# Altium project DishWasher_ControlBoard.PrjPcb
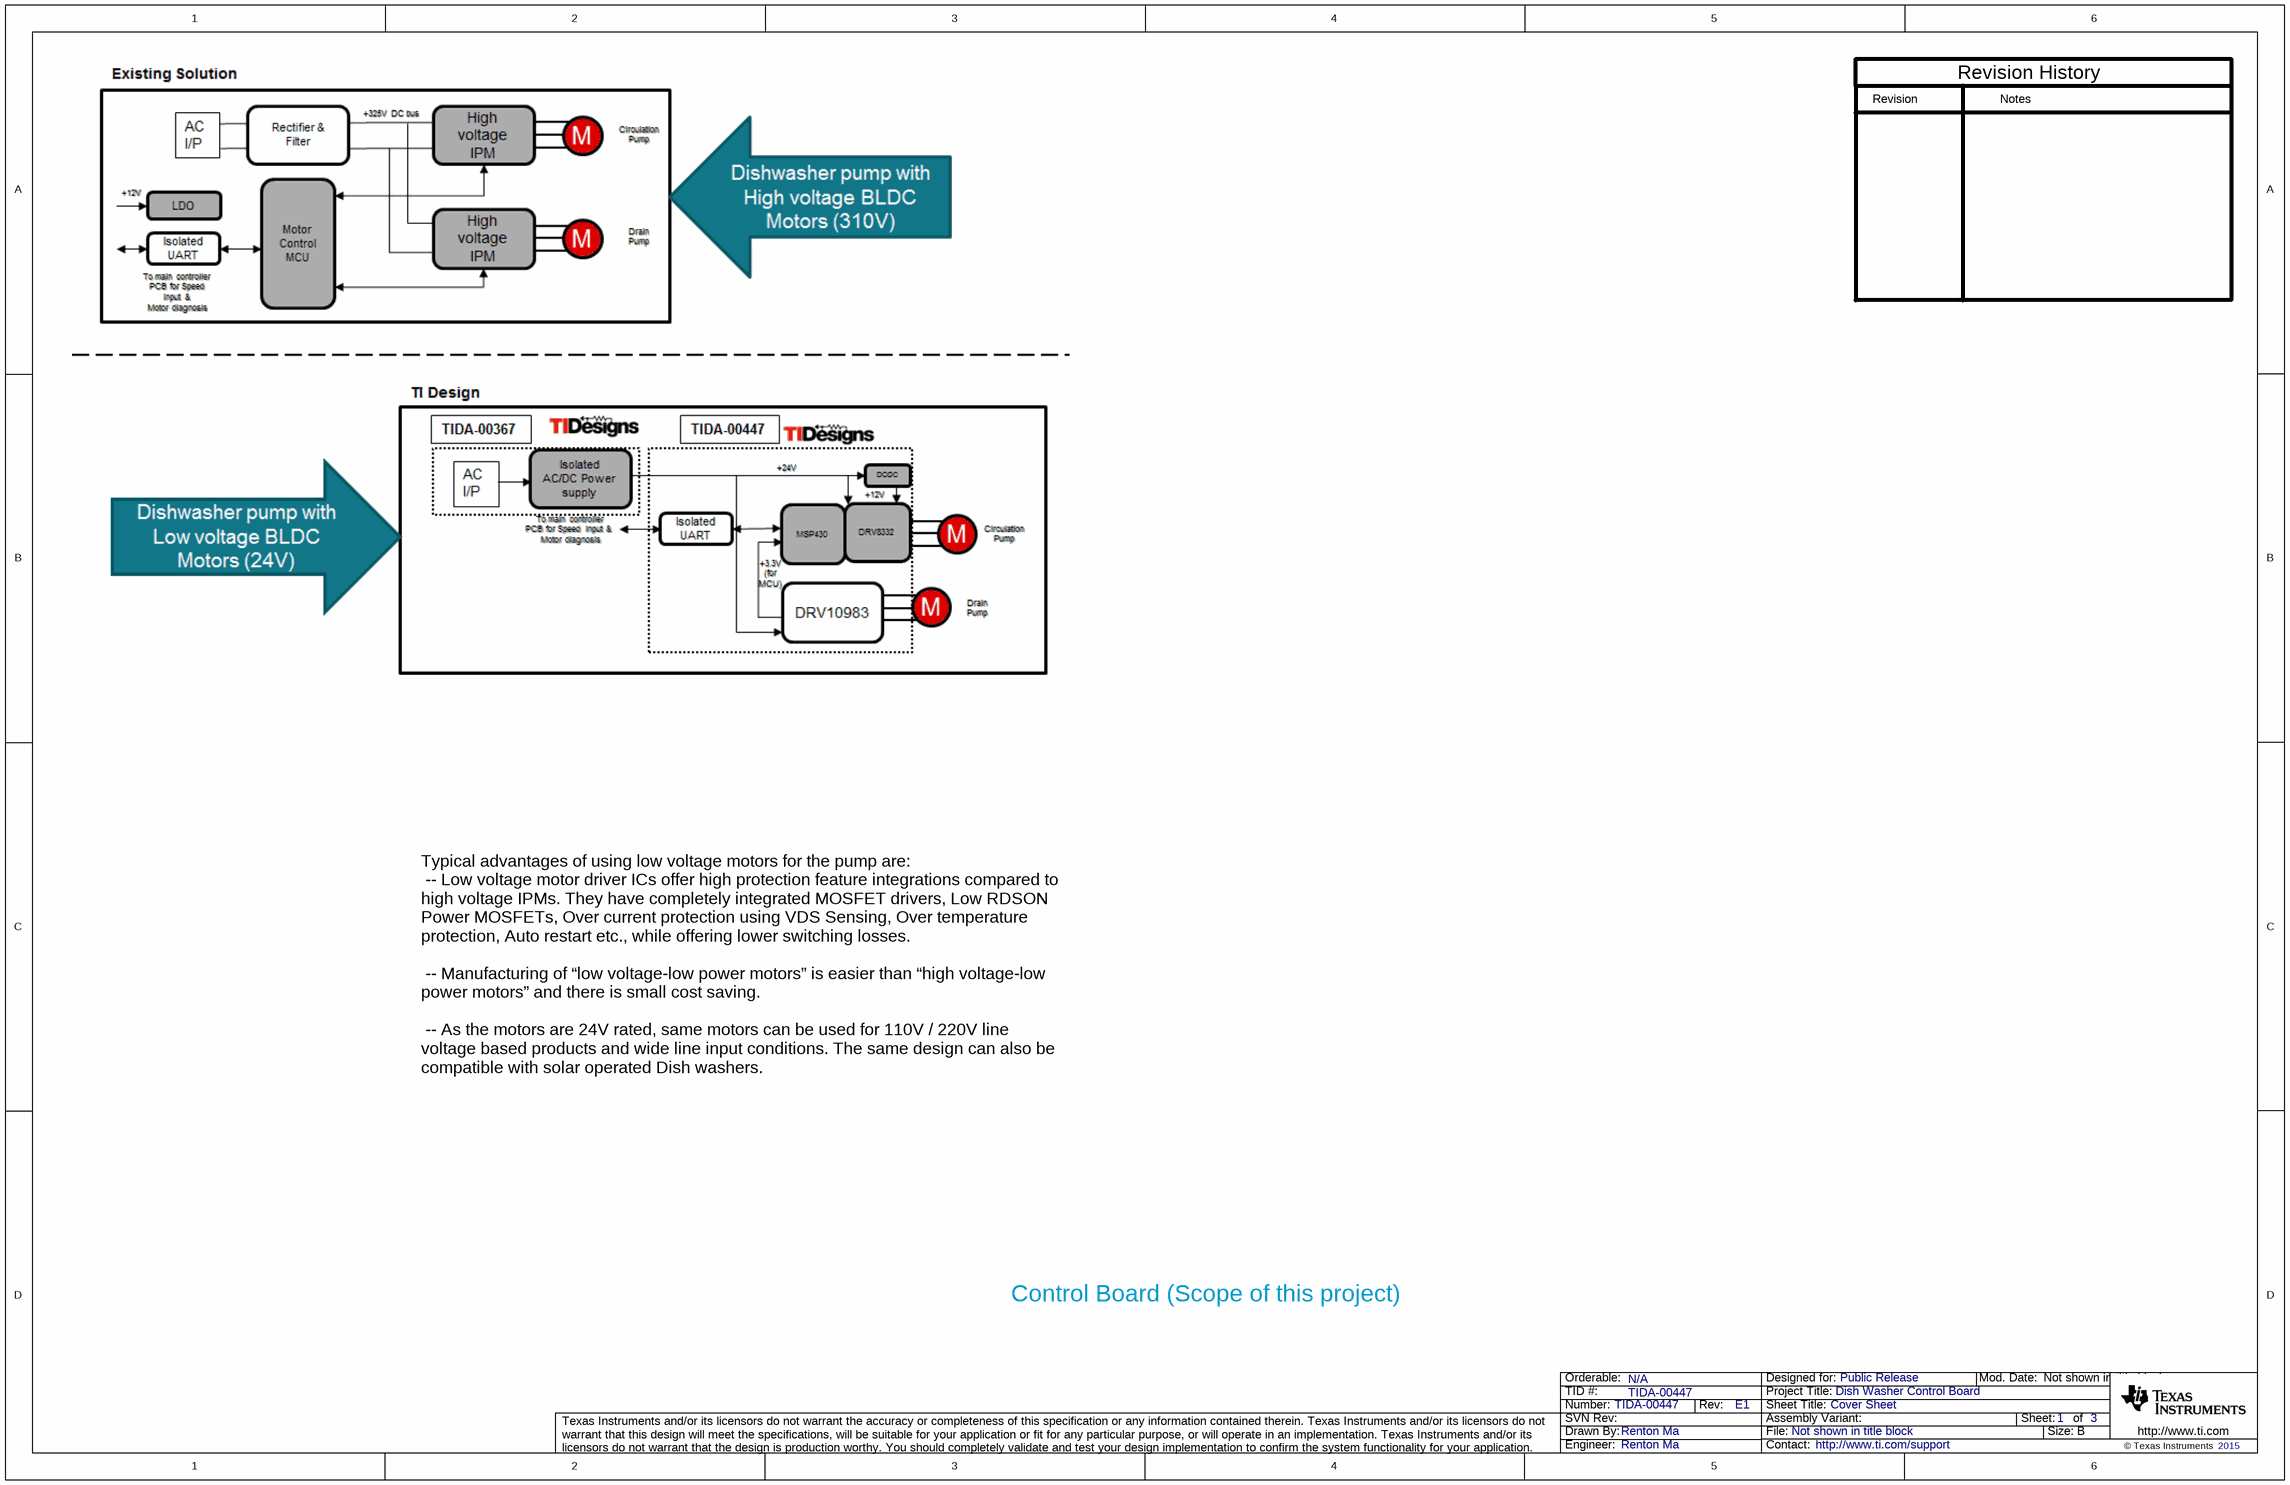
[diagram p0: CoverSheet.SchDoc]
CopyrightYear: 2015; EVM_Orderable: N/A; PCB_Layout: Who did the Layout?; PCB_Rev: E1; PRJ_Customer: Public Release; PRJ_Engineer: Renton Ma; PRJ_Number: TIDA-00447; PRJ_Title: Dish Washer Control Board; SCH_Rev: E1; TechSupport: http://www.ti.com/support; TID: TIDA-00447
4 sheets, 147 parts. Net scope: global (net labels, ports and power ports of the same name join across sheets).
Board file: TIDA00447.PcbDoc
Sheets:
  CoverSheet.SchDoc
  TID_Hardware.SchDoc
  TIDA00447_MCU+DRV10983.SchDoc
  TIDA00447_DRV8303.SchDoc

## Sheet CoverSheet.SchDoc: Cover Sheet
size 431 x 279 mm; IsUserConfigurable: Yes; Date: Not shown in title block; ApprovedBy: Not shown in title block; CheckedBy: Not shown in title block; Author: Not shown in title block; CompanyName: Not shown in title block; DrawnBy: Renton Ma; Engineer: Renton Ma; Organization: Not shown in title block; Address1: Not shown in title block; Address2: Not shown in title block; Address3: Not shown in title block; Address4: Not shown in title block; DocumentNumber: 1; Revision: Use project parameter SCH_Rev; SheetNumber: 1; SheetTotal: 3; PageSetup: Record=PageOptions¦CenterHorizontal=True¦CenterVertical=True¦PrintScale=1.00¦XCorrection=1.00¦YCorrection=1.00¦PrintKind=0¦BorderSize=5000000¦LeftOffset=0¦BottomOffset=0¦Orientation=2¦PaperLength=1000¦PaperWidth=1000¦Scale=100¦PaperSource=15¦PrintQuality=600¦MediaType=1¦DitherType=10¦PaperKind=Letter¦PrintScaleMode=1

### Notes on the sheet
- Revision
- Notes
- Revision History
- Typical advantages of using low voltage motors for the pump are:
  -- Low voltage motor driver ICs offer high protection feature integrations compared to high voltage IPMs. They have completely integrated MOSFET drivers, Low RDSON Power MOSFETs, Over current protection using VDS Sensing, Over temperature protection, Auto restart etc., while offering lower switching losses.
  -- Manufacturing of “low voltage-low power motors” is easier than “high voltage-low power motors” and there is small cost saving.
  -- As the motors are 24V rated, same motors can be used for 110V / 220V line voltage based products and wide line input conditions. The same design can also be compatible with solar operated Dish washers.
- Control Board (Scope of this project)

## Sheet TID_Hardware.SchDoc
size 431 x 279 mm; Date: Not shown in title block; ApprovedBy: Not shown in title block; CheckedBy: Not shown in title block; Author: Not shown in title block; CompanyName: Not shown in title block; Engineer: Not shown in title block; Organization: Not shown in title block; Address1: Not shown in title block; Address2: Not shown in title block; Address3: Not shown in title block; Address4: Not shown in title block; DocumentNumber: 1; Revision: Use project parameter SCH_Rev; SheetNumber: 3; SheetTotal: 3; PageSetup: Record=PageOptions¦CenterHorizontal=True¦CenterVertical=True¦PrintScale=1.00¦XCorrection=1.00¦YCorrection=1.00¦PrintKind=0¦BorderSize=5000000¦LeftOffset=0¦BottomOffset=0¦Orientation=2¦PaperLength=1000¦PaperWidth=1000¦Scale=100¦PaperSource=15¦PrintQuality=600¦MediaType=1¦DitherType=10¦PaperKind=Letter¦PrintScaleMode=1
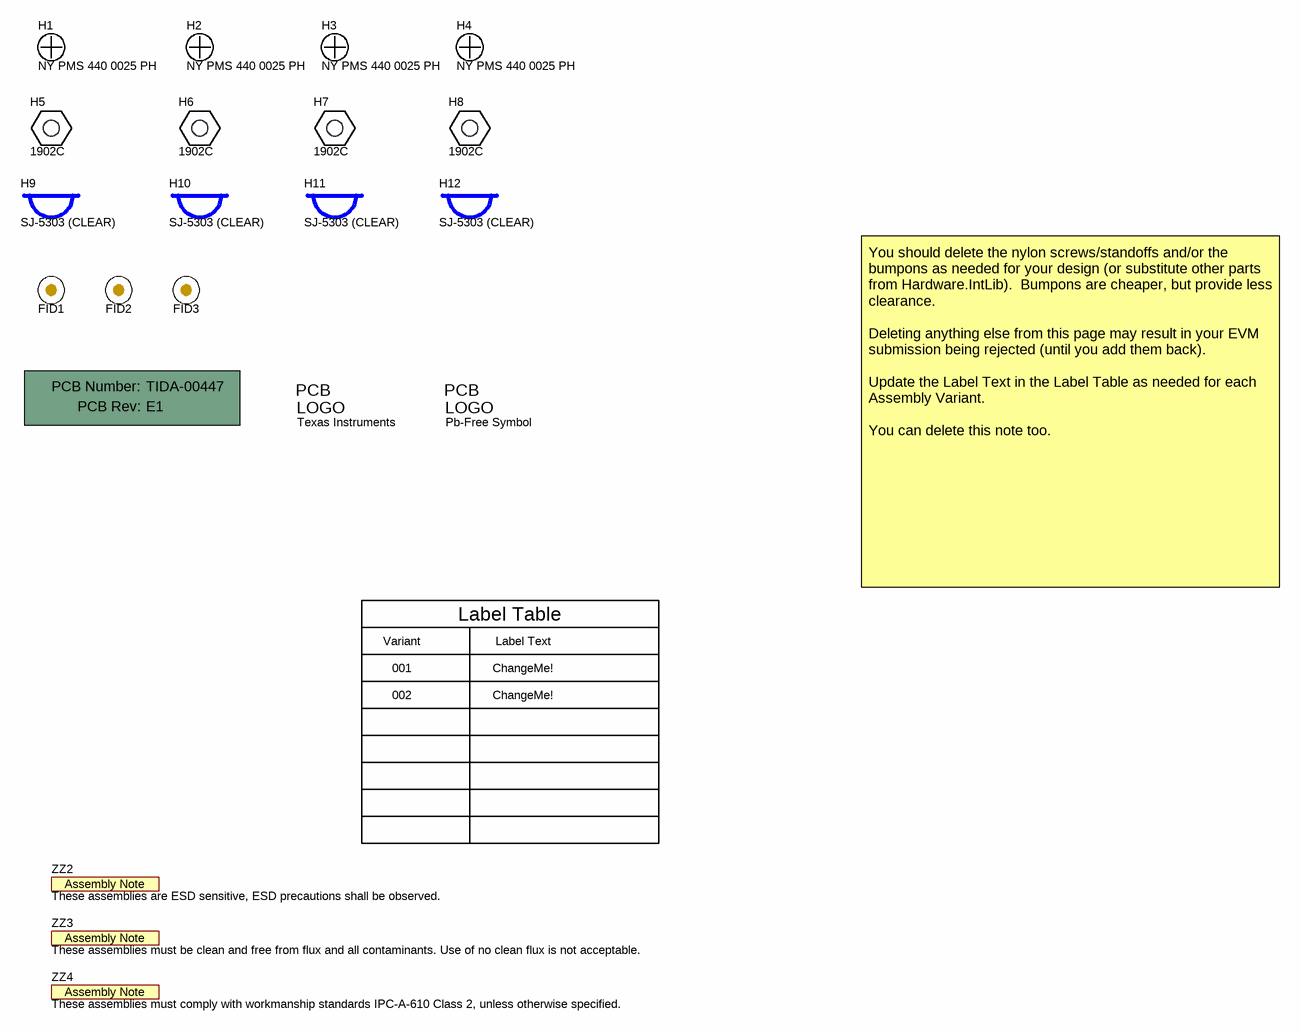
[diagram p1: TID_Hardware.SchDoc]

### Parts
!PCB  Printed Circuit Board  (value not drawn)  (mechanical)
FID1  Fiducial  [Fiducial10-20]  (value not drawn)
FID2  Fiducial  [Fiducial10-20]  (value not drawn)
FID3  Fiducial  [Fiducial10-20]  (value not drawn)
H1  NY PMS 440 0025 PH  [NY PMS 440 0025 PH]
H2  NY PMS 440 0025 PH  [NY PMS 440 0025 PH]
H3  NY PMS 440 0025 PH  [NY PMS 440 0025 PH]
H4  NY PMS 440 0025 PH  [NY PMS 440 0025 PH]
H5  1902C  [Keystone_1902C]
H6  1902C  [Keystone_1902C]
H7  1902C  [Keystone_1902C]
H8  1902C  [Keystone_1902C]
H9  SJ-5303 (CLEAR)  [Bumpon_SJ5003Transparent]
H10  SJ-5303 (CLEAR)  [Bumpon_SJ5003Transparent]
H11  SJ-5303 (CLEAR)  [Bumpon_SJ5003Transparent]
H12  SJ-5303 (CLEAR)  [Bumpon_SJ5003Transparent]
Logo1  Texas Instruments  [TI_Stacked_SolderMask_Small]  (no BOM)
Logo2  Pb-Free Symbol  [Pb-Free_Overlay_Small]  (no BOM)
ZZ2  These assemblies are ESD sensitive, ESD precautions shall be observed.  [AssemblyNote]  (no BOM)
ZZ3  These assemblies must be clean and free from flux and all contaminants. Use of no clean flux is not acceptable.  [AssemblyNote]  (no BOM)
ZZ4  These assemblies must comply with workmanship standards IPC-A-610 Class 2, unless otherwise specified.  [AssemblyNote]  (no BOM)

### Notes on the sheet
- Variant
- Label Table
- Label Text
- You should delete the nylon screws/standoffs and/or the bumpons as needed for your design (or substitute other parts from Hardware.IntLib).  Bumpons are cheaper, but provide less clearance.
  Deleting anything else from this page may result in your EVM submission being rejected (until you add them back).
  Update the Label Text in the Label Table as needed for each Assembly Variant.
  You can delete this note too.
- 001
- 002
- ChangeMe!

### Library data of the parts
!PCB = PCB: Manufacturer: Any; PartNumber: TIDA-00447; SymbolCreator: a0412235
FID1-FID3 = Fiducial: Fiducial mark.  There is nothing to buy or mount.; SymbolCreator: codlsc
H1-H4 = NY PMS 440 0025 PH: Machine Screw, Round, #4-40 x 1/4, Nylon, Philips panhead; Manufacturer: B&F Fastener Supply; CompType: Hardware; SymbolCreator: codlsc; U/M: EA
H5-H8 = 1902C: Standoff, Hex, 0.5"L #4-40 Nylon; Manufacturer: Keystone; CompType: Hardware
H9-H12 = SJ-5303 (CLEAR): Bumpon, Hemisphere, 0.44 X 0.20, Clear; Manufacturer: 3M; SymbolCreator: a0412235
Logo1 = TI_Logo: Texas Instrument Corporate Signature; SymbolCreator: codlsc
Logo2 = Pb-Free: SymbolCreator: a0412235
ZZ2-ZZ4 = AssemblyNote: SymbolCreator: codlsc

## Sheet TIDA00447_MCU+DRV10983.SchDoc: Pump Drivers
size 431 x 279 mm; Date: Not shown in title block; ApprovedBy: Not shown in title block; CheckedBy: Not shown in title block; Author: Not shown in title block; CompanyName: Not shown in title block; Engineer: Not shown in title block; Organization: Not shown in title block; Address1: Not shown in title block; Address2: Not shown in title block; Address3: Not shown in title block; Address4: Not shown in title block; DocumentNumber: 1; Revision: Use project parameter SCH_Rev; SheetNumber: 2; SheetTotal: 3; PageSetup: Record=PageOptions¦CenterHorizontal=True¦CenterVertical=True¦PrintScale=0.62¦XCorrection=1.00¦YCorrection=1.00¦PrintKind=0¦BorderSize=5000000¦LeftOffset=0¦BottomOffset=0¦Orientation=2¦PaperLength=1000¦PaperWidth=1000¦Scale=100¦PaperSource=15¦PrintQuality=600¦MediaType=1¦DitherType=10¦PaperKind=Letter¦PrintScaleMode=1
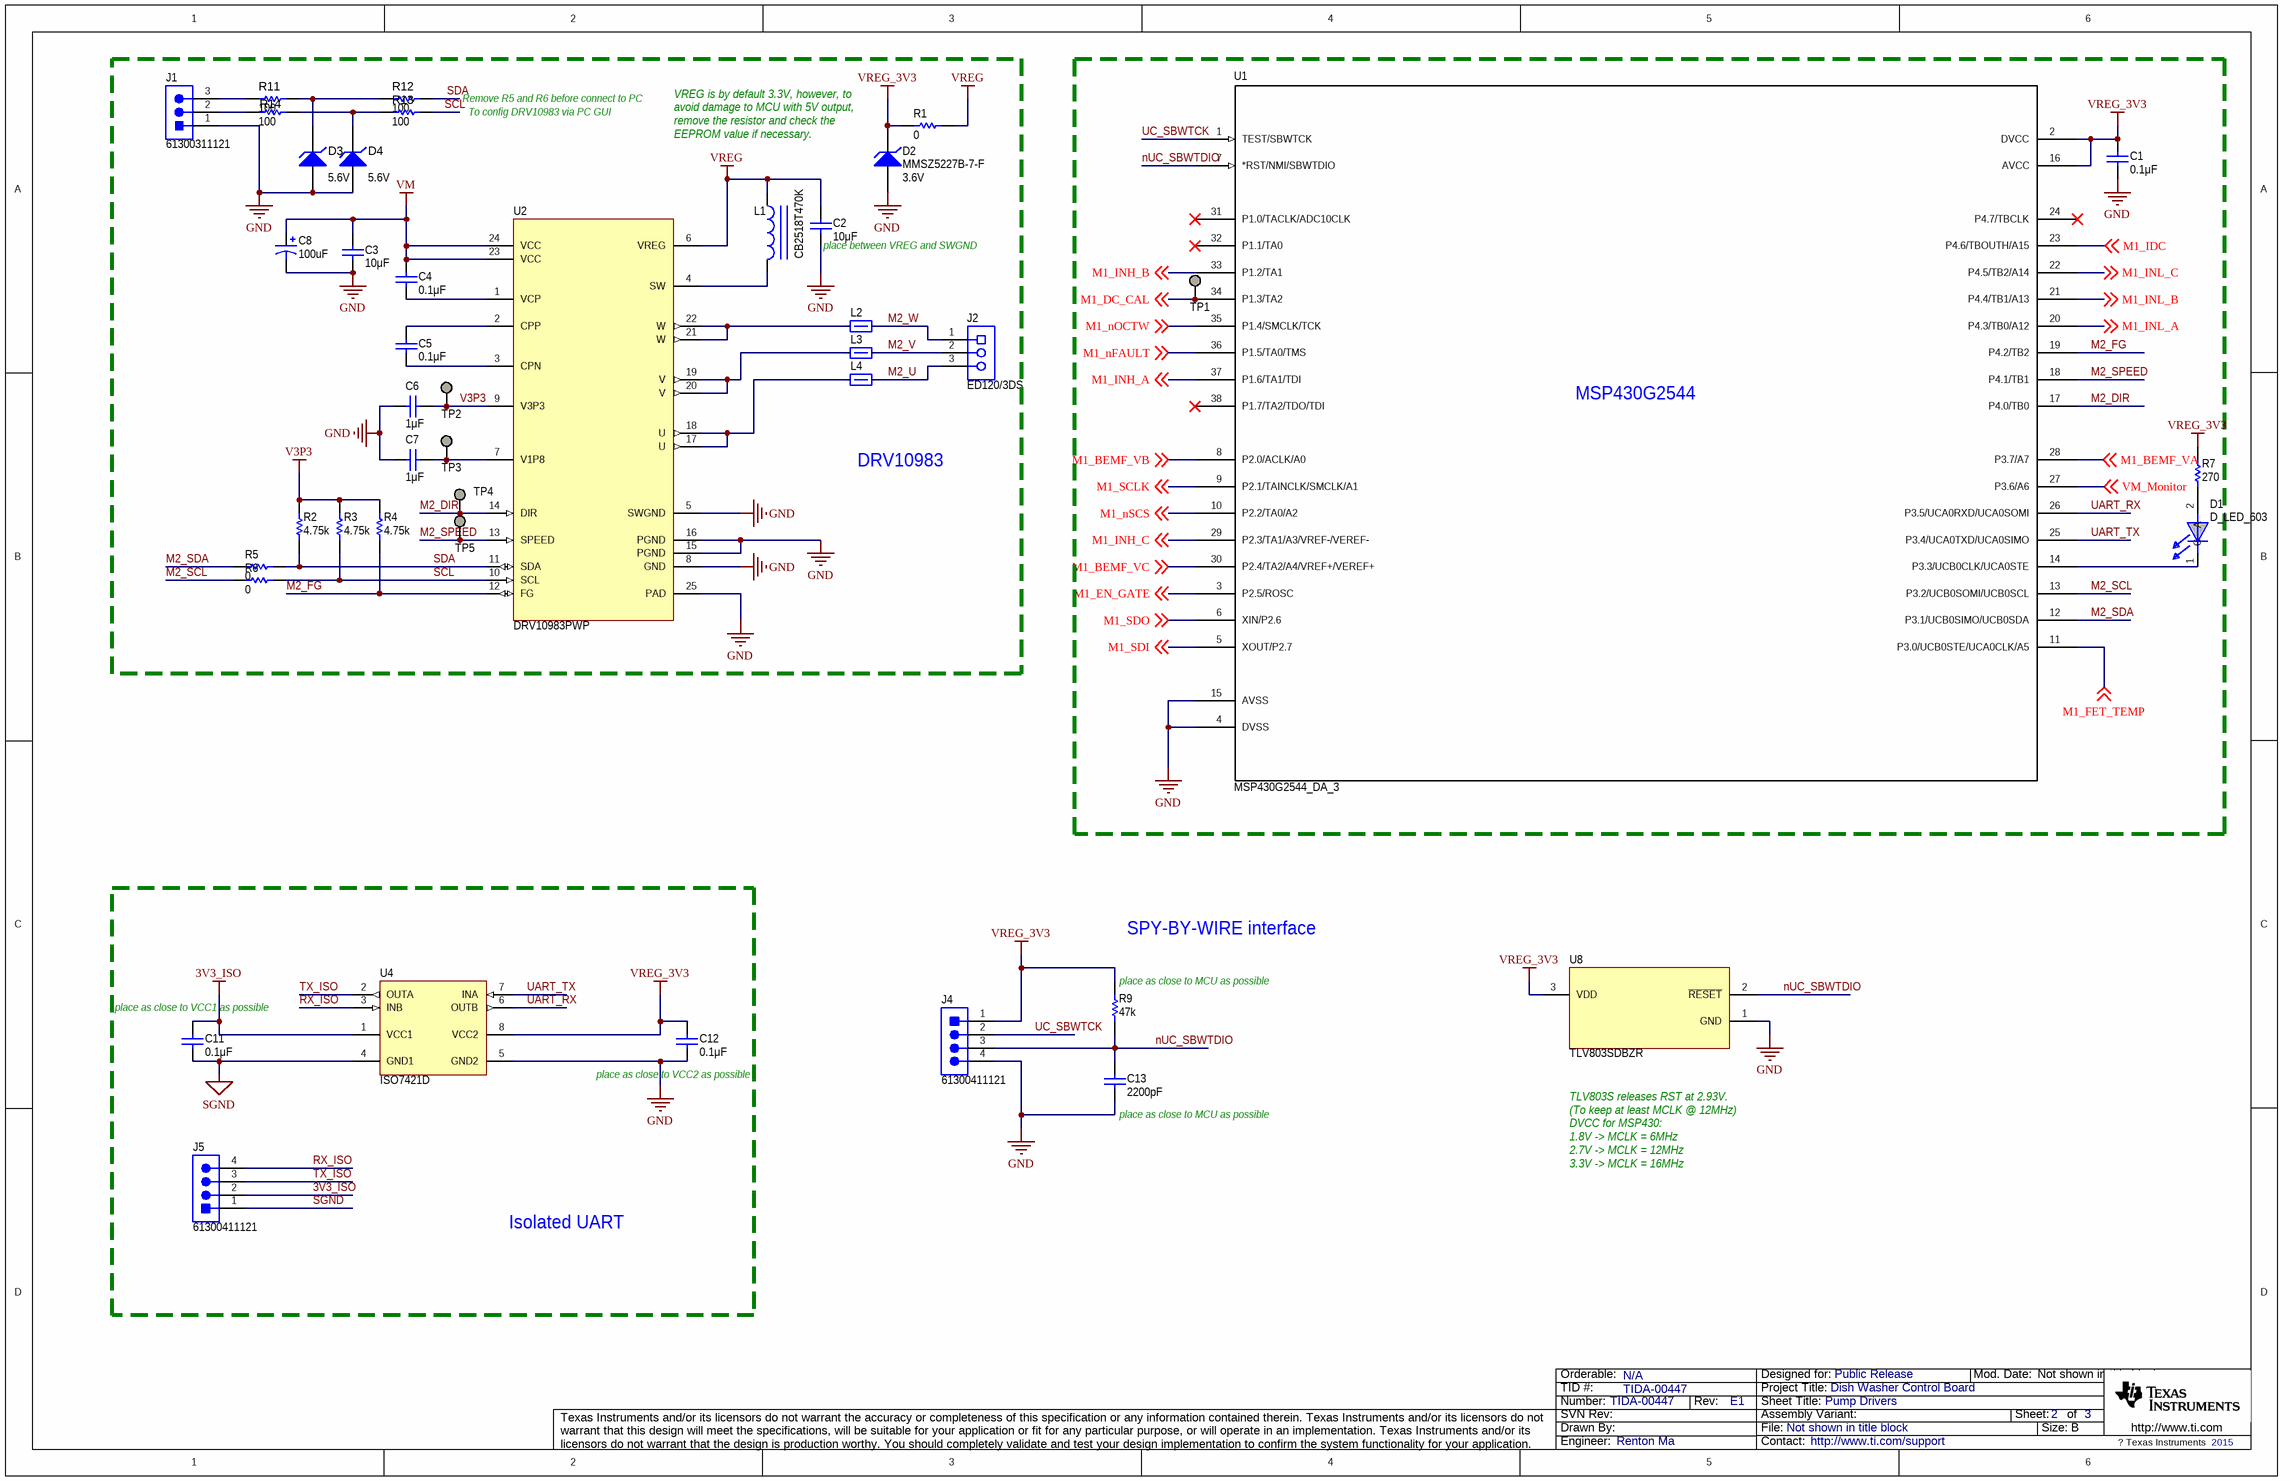
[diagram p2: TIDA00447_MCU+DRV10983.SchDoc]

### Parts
C1  ValueDisplayed: 0.1μF  [0603]  (hidden comment: C1608X8R1E104K)
C2  ValueDisplayed: 10μF  [0603]  (hidden comment: C1608X5R1A106M)
C3  ValueDisplayed: 10μF  [1210_280]  (hidden comment: GRM32ER61H106KA12L)
C4  ValueDisplayed: 0.1μF  [0603]  (hidden comment: C1608X7R1H104K)
C5  ValueDisplayed: 0.1μF  [0603]  (hidden comment: C1608X7R1H104K)
C6  ValueDisplayed: 1μF  [0603]  (hidden comment: C1608X5R0J105K)
C7  ValueDisplayed: 1μF  [0603]  (hidden comment: C1608X5R0J105K)
C8  ValueDisplayed: 100uF  [CAPSMT_62_F60]  (hidden comment: APXA6R3ARA101MF60G)
C11  ValueDisplayed: 0.1μF  [0603]  (hidden comment: C1608X8R1E104K)
C12  ValueDisplayed: 0.1μF  [0603]  (hidden comment: C1608X8R1E104K)
C13  ValueDisplayed: 2200pF  [0603]  (hidden comment: C1608X7R1H222K)
D1  D_LED_603  [LED603]
D2  MMSZ5227B-7-F  value 3.6V  [SOD-123]
D3  value 5.6V  [sod-323]  (hidden comment: MMSZ5232BS-7-F)
D4  value 5.6V  [sod-323]  (hidden comment: MMSZ5232BS-7-F)
J1  61300311121  [WURTH_61300311121]
J2  ED120/3DS  [CONN_ED120_3DS]
J4  61300411121  [WURTH_61300411121]
J5  61300411121  [WURTH_61300411121]
L1  CB2518T470K  [IND_CB2518]
L2  MPZ2012S300A  [MPZ2012]  (value not drawn)
L3  MPZ2012S300A  [MPZ2012]  (value not drawn)
L4  MPZ2012S300A  [MPZ2012]  (value not drawn)
R1  ValueDisplayed: 0  [2010]  (hidden comment: CRCW20100000Z0EF)
R2  ValueDisplayed: 4.75k  [0603]  (hidden comment: CRCW06034K75FKEA)
R3  ValueDisplayed: 4.75k  [0603]  (hidden comment: CRCW06034K75FKEA)
R4  ValueDisplayed: 4.75k  [0603]  (hidden comment: CRCW06034K75FKEA)
R5  ValueDisplayed: 0  [0603]  (hidden comment: RC0603JR-070RL)
R6  ValueDisplayed: 0  [0603]  (hidden comment: RC0603JR-070RL)
R7  ValueDisplayed: 270  [0603]  (hidden comment: CRCW0603270RJNEA)
R9  ValueDisplayed: 47k  [0603]  (hidden comment: CRCW060347K0JNEA)
R11  ValueDisplayed: 100  [0603]  (hidden comment: CRCW0603100RJNEA)
R12  ValueDisplayed: 100  [0603]  (hidden comment: CRCW0603100RJNEA)
R13  ValueDisplayed: 100  [0603]  (hidden comment: CRCW0603100RJNEA)
R14  ValueDisplayed: 100  [0603]  (hidden comment: CRCW0603100RJNEA)
TP1  DC_CAL  [TESTPOINT]  (value not drawn)  (no BOM)
TP2  V3P3  [TESTPOINT]  (value not drawn)  (no BOM)
TP3  V1P8  [TESTPOINT]  (value not drawn)  (no BOM)
TP4  DIR  [TESTPOINT]  (value not drawn)  (no BOM)
TP5  SPEED  [TESTPOINT]  (value not drawn)  (no BOM)
U1  MSP430G2544_DA_3  [IC-TSSOP38-DA]
U2  DRV10983PWP  [PWP0024B_N]
U4  ISO7421D  [D0008A_N]
U8  TLV803SDBZR  [DBZ0003A_N]

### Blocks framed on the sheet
DRV10983: C2-C8 D2-D4 J1 J2 L1-L4 R1-R6 R11-R14 TP2-TP5 U2
MSP430G2544: C1 D1 R7 TP1 U1
Isolated UART: C11 C12 J5 U4

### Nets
3V3_ISO: C11.1 J5.2 U4.1(VCC1)
GND: C1.2 C2.2 C3.1 C6.2 C7.1 C8.2(-) C12.2 C13.2 D2.2(A) D3.2(A) D4.2(A) J1.1 J4.4 U1.4(DVSS) U1.15(AVSS) U2.5(SWGND) U2.8(GND) U2.15(PGND) U2.16(PGND) U2.25(PAD) U4.5(GND2) U8.1(GND)
SGND: C11.2 J5.1 U4.4(GND1)
V3P3: C6.1 R2.2 R3.2 R4.2 TP2.1 U2.9(V3P3)
VM: C3.2 C4.1 C8.1(+) U2.23(VCC) U2.24(VCC)
VREG: C2.1 L1.1 R1.2 U2.6(VREG)
VREG_3V3: C1.1 C12.1 D2.1(K) J4.1 R1.1 R7.2 R9.2 U1.2(DVCC) U1.16(AVCC) U4.8(VCC2) U8.3(VDD)
M1_BEMF_VA: U1.28(P3.7/A7) ; off-sheet M1_BEMF_VA
M1_BEMF_VB: U1.8(P2.0/ACLK/A0) ; off-sheet M1_BEMF_VB
M1_BEMF_VC: U1.30(P2.4/TA2/A4/VREF+/VEREF+) ; off-sheet M1_BEMF_VC
M1_DC_CAL: TP1.1 U1.34(P1.3/TA2) ; off-sheet M1_DC_CAL
M1_EN_GATE: U1.3(P2.5/ROSC) ; off-sheet M1_EN_GATE
M1_FET_TEMP: U1.11(P3.0/UCB0STE/UCA0CLK/A5) ; off-sheet M1_FET_TEMP
M1_IDC: U1.23(P4.6/TBOUTH/A15) ; off-sheet M1_IDC
M1_INH_A: U1.37(P1.6/TA1/TDI) ; off-sheet M1_INH_A
M1_INH_B: U1.33(P1.2/TA1) ; off-sheet M1_INH_B
M1_INH_C: U1.29(P2.3/TA1/A3/VREF-/VEREF-) ; off-sheet M1_INH_C
M1_INL_A: U1.20(P4.3/TB0/A12) ; off-sheet M1_INL_A
M1_INL_B: U1.21(P4.4/TB1/A13) ; off-sheet M1_INL_B
M1_INL_C: U1.22(P4.5/TB2/A14) ; off-sheet M1_INL_C
M1_nFAULT: U1.36(P1.5/TA0/TMS) ; off-sheet M1_nFAULT
M1_nOCTW: U1.35(P1.4/SMCLK/TCK) ; off-sheet M1_nOCTW
M1_nSCS: U1.10(P2.2/TA0/A2) ; off-sheet M1_nSCS
M1_SCLK: U1.9(P2.1/TAINCLK/SMCLK/A1) ; off-sheet M1_SCLK
M1_SDI: U1.5(XOUT/P2.7) ; off-sheet M1_SDI
M1_SDO: U1.6(XIN/P2.6) ; off-sheet M1_SDO
M2_DIR: TP4.1 U1.17(P4.0/TB0) U2.14(DIR)
M2_FG: R4.1 U1.19(P4.2/TB2) U2.12(FG)
M2_SCL: R6.1 U1.13(P3.2/UCB0SOMI/UCB0SCL)
M2_SDA: R5.1 U1.12(P3.1/UCB0SIMO/UCB0SDA)
M2_SPEED: TP5.1 U1.18(P4.1/TB1) U2.13(SPEED)
M2_U: J2.3 L4.2
M2_V: J2.2 L3.2
M2_W: J2.1 L2.2
nUC_SBWTDIO: C13.1 J4.3 R9.1 U1.7(*RST/NMI/SBWTDIO) U8.2(~{RESET})
RX_ISO: J5.4 U4.3(INB)
SCL: R3.1 R6.2 R13.2 U2.10(SCL)
SDA: R2.1 R5.2 R12.2 U2.11(SDA)
TX_ISO: J5.3 U4.2(OUTA)
UART_RX: U1.26(P3.5/UCA0RXD/UCA0SOMI) U4.6(OUTB)
UART_TX: U1.25(P3.4/UCA0TXD/UCA0SIMO) U4.7(INA)
UC_SBWTCK: J4.2 U1.1(TEST/SBWTCK)
VM_Monitor: U1.27(P3.6/A6) ; off-sheet VM_Monitor
NetC4_2: C4.2 U2.1(VCP)
NetC5_1: C5.1 U2.2(CPP)
NetC5_2: C5.2 U2.3(CPN)
NetC7_2: C7.2 TP3.1 U2.7(V1P8)
NetD1_1: D1.1(C) U1.14(P3.3/UCB0CLK/UCA0STE)
NetD1_2: D1.2(A) R7.1
NetD3_1: D3.1(K) R11.2 R12.1
NetD4_1: D4.1(K) R13.1 R14.2
NetJ1_2: J1.2 R14.1
NetJ1_3: J1.3 R11.1
NetL1_2: L1.2 U2.4(SW)
NetL2_1: L2.1 U2.21(W) U2.22(W)
NetL3_1: L3.1 U2.19(V) U2.20(V)
NetL4_1: L4.1 U2.17(U) U2.18(U)

Not connected (* = marked no-connect by the designer): U1 24(P4.7/TBCLK)* 31(P1.0/TACLK/ADC10CLK)* 32(P1.1/TA0)* 38(P1.7/TA2/TDO/TDI)*

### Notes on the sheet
- Remove R5 and R6 before connect to PC
- To config DRV10983 via PC GUI
- (near D2) VREG is by default 3.3V, however, to avoid damage to MCU with 5V output,
  remove the resistor and check the EEPROM value if necessary.
- (near C2) place between VREG and SWGND
- SPY-BY-WIRE interface
- (near C11) place as close to VCC1 as possible
- (near R9) place as close to MCU as possible
- (near C12) place as close to VCC2 as possible
- (near C13) place as close to MCU as possible
- TLV803S releases RST at 2.93V.
  (To keep at least MCLK @ 12MHz)
  DVCC for MSP430:
  1.8V -> MCLK = 6MHz
  2.7V -> MCLK = 12MHz
  3.3V -> MCLK = 16MHz

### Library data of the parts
C1 C11 C12 = C1608X8R1E104K: CAP, CERM, 0.1 μF, 25 V, +/- 10%, X8R, 0603; Manufacturer: TDK; Polarized: N; CompType: Capacitor; Value: 0.1uF; U/M: EA; Cap_F: 0.0000001; Tolerance_%: 10; ESR_ohm: 0.0131; Value1: 0.0131 ohm; VDC_V: 25; Value2: 25V; TaMin_C: -55; TaMax_C: 150
C2 = C1608X5R1A106M: CAP, CERM, 10 μF, 10 V, +/- 20%, X5R, 0603; Manufacturer: TDK; Polarized: N; CompType: Capacitor; Value: 10uF; U/M: EA; Cap_F: 0.00001; Tolerance_%: 20; ESR_ohm: 0.0078; Value1: 0.0078 ohm; VDC_V: 10; Value2: 10V; IRMS_A: 1.85; TaMin_C: -55; TaMax_C: 85
C3 = GRM32ER61H106KA12L: CAP, CERM, 10 μF, 50 V, +/- 10%, X5R, 1210; Manufacturer: MuRata; Polarized: N; CompType: Capacitor; Value: 10uF; U/M: EA; Cap_F: 0.00001; Tolerance_%: 10; Value1: Unknown; VDC_V: 50; Value2: 50V; TaMin_C: -55; TaMax_C: 85; Cap_Case: 1210
C4 C5 = C1608X7R1H104K: CAP, CERM, 0.1 μF, 50 V, +/- 10%, X7R, 0603; Manufacturer: TDK; Polarized: N; CompType: Capacitor; Value: 0.1uF; U/M: EA; Cap_F: 0.0000001; Tolerance_%: 10; ESR_ohm: 0.017; Value1: 0.017 ohm; VDC_V: 50; Value2: 50V; TaMin_C: -55; TaMax_C: 125
C6 C7 = C1608X5R0J105K: CAP, CERM, 1 μF, 6.3 V, +/- 10%, X5R, 0603; Manufacturer: TDK; Polarized: N; CompType: Capacitor; Value: 1uF; U/M: EA; Cap_F: 0.000001; Tolerance_%: 10; ESR_ohm: 0.0057; Value1: 0.0057 ohm; VDC_V: 6.3; Value2: 6.3V; TaMin_C: -55; TaMax_C: 85
C8 = APXA6R3ARA101MF60G: CAP, AL, 100uF, 6.3V, +/-20%, 0.027 ohm, SMD; Manufacturer: Nippon Chemi-Con; Polarized: Y; CompType: Capacitor; U/M: EA; Cap_F: 0.0001; Tolerance_%: 20; VDC_V: 6.3; ESR_Ohm: 0.027; IRMS_A: 2.4; TaMin_C: -55; TaMax_C: 105; Cap_Case: F60
C13 = C1608X7R1H222K: CAP, CERM, 2200 pF, 50 V, +/- 10%, X7R, 0603; Manufacturer: TDK; Polarized: N; CompType: Capacitor; Value: 2200pF; U/M: EA; Cap_F: 0.0000000022; Tolerance_%: 10; ESR_ohm: 0.145; Value1: 0.145 ohm; VDC_V: 50; Value2: 50V; TaMin_C: -55; TaMax_C: 125
D1 = D_LED_603: Diode, LED, [Color], x-V, 20-mA, y-mcd; PartNumber: LTST-C190xKT; Manufacturer: Lite On; Area: 9450; Value: LTST-C190xKT
D2 = MMSZ5227B-7-F: Diode, Zener, 3.6 V, 500 mW, SOD-123; Manufacturer: Diodes Inc.; SymbolCreator: a0412235; U/M: EA; Power_W: 0.5; Vz_V: 3.6; Value1: 0.5W; RJA_CperW: 350
D3 D4 = MMSZ5232BS-7-F: Diode, Zener, 5.6 V, 200 mW, SOD-323; Manufacturer: Diodes Inc.; SymbolCreator: a0412235; U/M: EA; Power_W: 0.2; Vz_V: 5.6; Value1: 0.2W; RJA_CperW: 350
J1 = 61300311121: Header, 2.54 mm, 3x1, Gold, TH; Manufacturer: Wurth Elektronik; SymbolCreator: a0799628; U/M: EA
J2 = ED120/3DS: TERMINAL BLOCK 5.08MM VERT 3POS, TH; Manufacturer: On-Shore Technology; SymbolCreator: a0412235; U/M: EA
J4 J5 = 61300411121: Header, 2.54 mm, 4x1, Gold, TH; Manufacturer: Wurth Elektronik; SymbolCreator: a0412235; U/M: EA
L1 = CB2518T470K: Inductor, Wirewound, Ferrite, 47 μH, 0.11 A, 1.235 ohm, SMD; Manufacturer: Taiyo Yuden; Value: 47uH; Ind_H: 47.0E-6; ValueDisplayed: 47μH; Imax_A: 0.11; Irms: 0.42A @ 40C rise; Isat: 0.11A @ 30% inductance drop; DCR_ohm: 1.235; Value2: 0.11A
L2-L4 = MPZ2012S101A: Ferrite Bead, 100 ohm @ 100 MHz, 4 A, 0805; Manufacturer: TDK; Value: 30 ohm; Imax_A: 6; DCR_ohm: 0.02; Value1: 0.02 ohm; Value2: 6A; ZTyp@100MHz_Ohm: 100
R1 = CRCW20100000Z0EF: RES, 0, 5%, 0.75 W, 2010; Manufacturer: Vishay-Dale; CompType: Resistor; Value: 0; Value_Code: 0000; Tolerance_%: 5; Power_W: 0.75; Value2: 0.75W; TempCo: ppm/C; EIA_Code: E24; U/M: EA
R2-R4 = CRCW06034K75FKEA: RES, 4.75 k, 1%, 0.1 W, 0603; Manufacturer: Vishay-Dale; CompType: Resistor; Value: 4.75k; Res_ohm: 4750; Value_Code: 4k75; Tolerance_%: 1; Power_W: 0.1; Value2: 0.1W; VDC_V: 75; TempCo: 100 ppm/C; EIA_Code: E96; U/M: EA
R5 R6 = RC0603JR-070RL: RES, 0, 5%, 0.1 W, 0603; Manufacturer: Yageo America; CompType: Resistor; Value: 0; Value_Code: 0000; Tolerance_%: 5; Power_W: 0.1; Value2: 0.1W; VDC_V: 50; TempCo: 200 ppm/C; EIA_Code: E24; U/M: EA
R7 = CRCW0603270RJNEA: RES, 270, 5%, 0.1 W, 0603; Manufacturer: Vishay-Dale; CompType: Resistor; Value: 270; Value_Code: 270R; Tolerance_%: 5; Power_W: 0.1; Value2: 0.1W; VDC_V: 75; TempCo: 200 ppm/C; EIA_Code: E24; U/M: EA
R9 = CRCW060347K0JNEA: RES, 47 k, 5%, 0.1 W, 0603; Manufacturer: Vishay-Dale; CompType: Resistor; Value: 47k; Res_ohm: 47000; Value_Code: 47k0; Tolerance_%: 5; Power_W: 0.1; Value2: 0.1W; VDC_V: 75; TempCo: 200 ppm/C; EIA_Code: E24; U/M: EA
R11-R14 = CRCW0603100RJNEA: RES, 100, 5%, 0.1 W, 0603; Manufacturer: Vishay-Dale; CompType: Resistor; Value: 100; Value_Code: 100R; Tolerance_%: 5; Power_W: 0.1; Value2: 0.1W; VDC_V: 75; TempCo: 200 ppm/C; EIA_Code: E24; U/M: EA
TP1-TP5 = TESTPOINT: TEST POINT.  No entry in BOM.
U1 = MSP430G2544_DA_3: Imported; Manufacturer_Part_Number: msp430g2544_da_38; Vendor: TEXAS INSTRUMENTS
U2 = DRV10983PWP: 12- to 24-V, Three-Phase, Sensorless BLDC Motor Driver, PWP0024B; Manufacturer: Texas Instruments; SymbolCreator: a0799628; CompType: IC; U/M: EA
U4 = ISO7421D: 1 Mbps Dual Channels, 1 / 1, Digital Isolator, 3.3 V / 5 V, -40 to +105 degC, 8-pin SOIC (D), Green (RoHS & no Sb/Br); Manufacturer: Texas Instruments; Alternate PartNumber: Equivalent; Datarate(Mbps): 1; Input Noise Filter: None; Insulation Rating(VRMS): 2500; Prop Delay(Max)(ns): 12; Rating: Catalog; Supply Voltage(s)(V): 3.3, 5; TTL/CMOS Input Threshold: TTL
U8 = TLV803SDBZR: 3-Pin Voltage Supervisors with Active-Low, Open-Drain Reset, DBZ0003A; Alternate PartNumber: TLV803SDBZT; Manufacturer: Texas Instruments; SymbolCreator: Altium; CompType: IC; U/M: EA

## Sheet TIDA00447_DRV8303.SchDoc
size 431 x 279 mm; Date: Not shown in title block; ApprovedBy: Not shown in title block; CheckedBy: Not shown in title block; Author: Not shown in title block; CompanyName: Not shown in title block; Engineer: Not shown in title block; Organization: Not shown in title block; Address1: Not shown in title block; Address2: Not shown in title block; Address3: Not shown in title block; Address4: Not shown in title block; DocumentNumber: 1; Revision: Use project parameter SCH_Rev; SheetNumber: 2; SheetTotal: 3; PageSetup: Record=PageOptions¦CenterHorizontal=True¦CenterVertical=True¦PrintScale=1.00¦XCorrection=1.00¦YCorrection=1.00¦PrintKind=0¦BorderSize=5000000¦LeftOffset=0¦BottomOffset=0¦Orientation=2¦PaperLength=1000¦PaperWidth=1000¦Scale=100¦PaperSource=15¦PrintQuality=600¦MediaType=1¦DitherType=10¦PaperKind=Letter¦PrintScaleMode=1
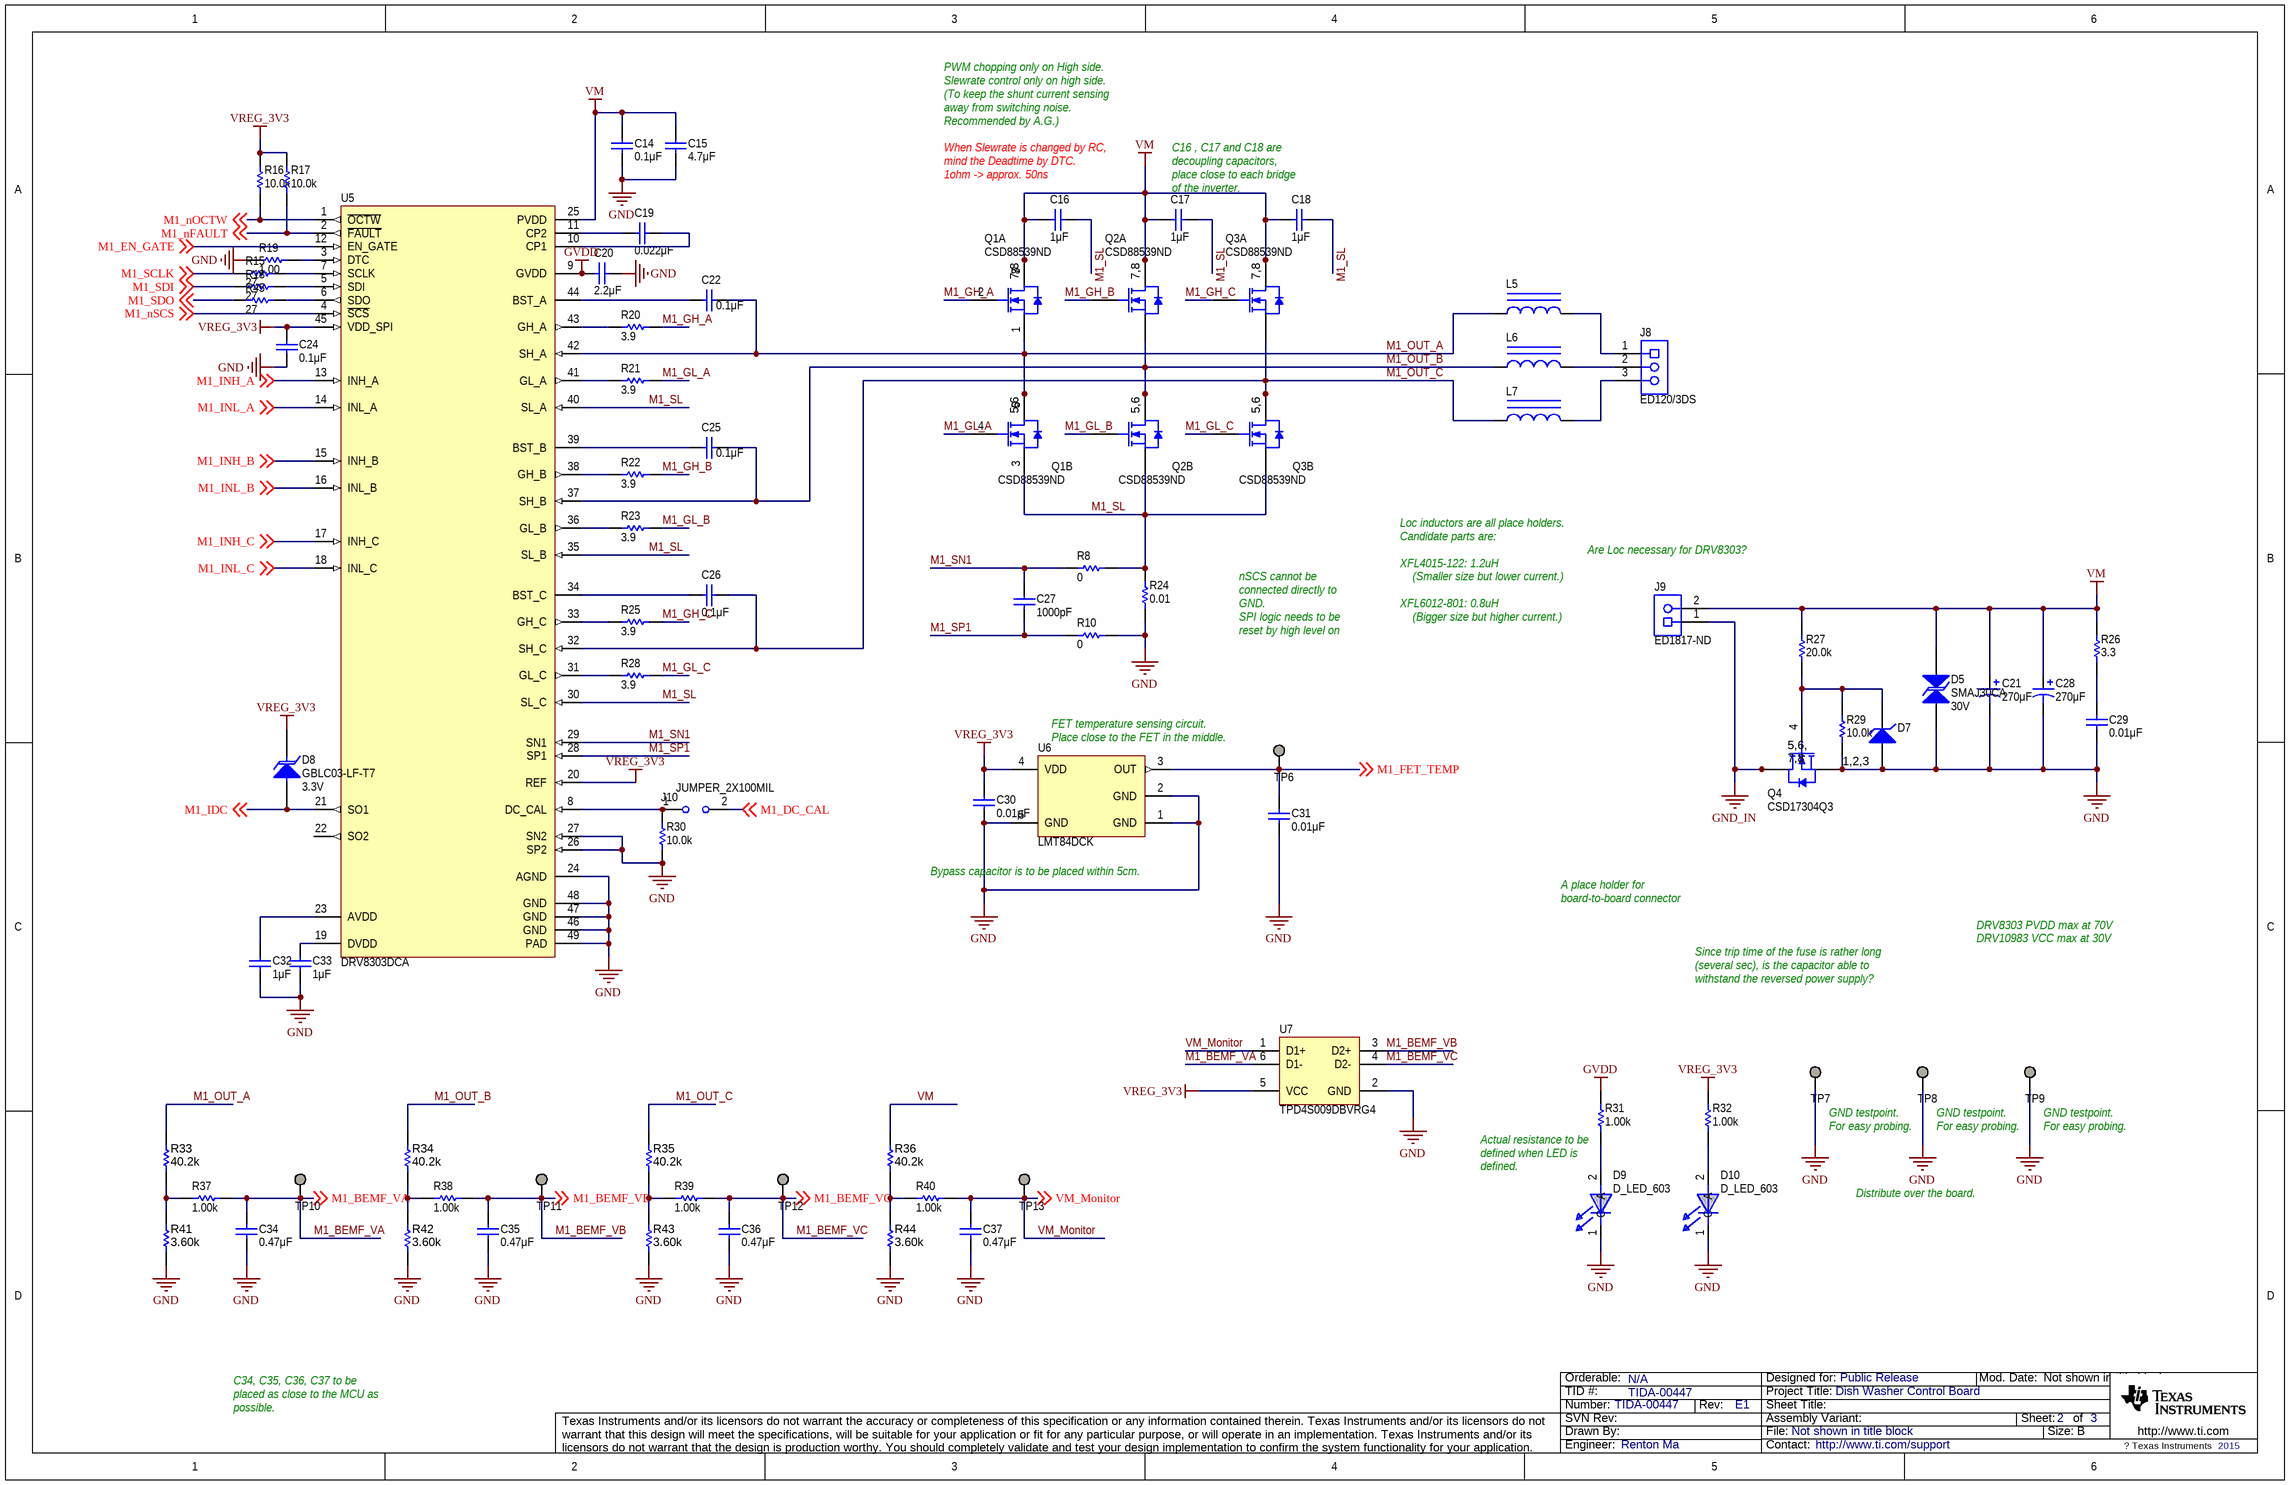
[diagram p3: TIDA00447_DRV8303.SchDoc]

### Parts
C14  ValueDisplayed: 0.1μF  [0603]  (hidden comment: 06035C104KAT2A)
C15  ValueDisplayed: 4.7μF  [0805_HV]  (hidden comment: C2012X5R1H475K125AB)
C16  ValueDisplayed: 1μF  [0805_HV]  (hidden comment: C2012X7R1H105K125AB)
C17  ValueDisplayed: 1μF  [0805_HV]  (hidden comment: C2012X7R1H105K125AB)
C18  ValueDisplayed: 1μF  [0805_HV]  (hidden comment: C2012X7R1H105K125AB)
C19  ValueDisplayed: 0.022μF  [0603]  (hidden comment: C1608X8R1H223K)
C20  ValueDisplayed: 2.2μF  [0805_HV]  (hidden comment: C2012X7R1V225K085AC)
C21  ValueDisplayed: 270μF  [SM_RADIAL_10BMM]  (hidden comment: EEHZA1V271P)
C22  ValueDisplayed: 0.1μF  [0603]  (hidden comment: 06035C104KAT2A)
C24  ValueDisplayed: 0.1μF  [0603]  (hidden comment: C0603X104K8RACTU)
C25  ValueDisplayed: 0.1μF  [0603]  (hidden comment: 06035C104KAT2A)
C26  ValueDisplayed: 0.1μF  [0603]  (hidden comment: 06035C104KAT2A)
C27  ValueDisplayed: 1000pF  [0603]  (hidden comment: C1608C0G1H102J)
C28  ValueDisplayed: 270μF  [SM_RADIAL_10BMM]  (hidden comment: EEHZA1V271P)
C29  ValueDisplayed: 0.01μF  [0805_HV]  (hidden comment: 08055C103JAT2A)
C30  ValueDisplayed: 0.01μF  [0603]  (hidden comment: C1608C0G1E103J)
C31  ValueDisplayed: 0.01μF  [0603]  (hidden comment: C1608C0G1E103J)
C32  ValueDisplayed: 1μF  [0603]  (hidden comment: C1608X5R1E105K080AC)
C33  ValueDisplayed: 1μF  [0603]  (hidden comment: C1608X5R1E105K080AC)
C34  ValueDisplayed: 0.47μF  [0603]  (hidden comment: C1608X5R1A474K)
C35  ValueDisplayed: 0.47μF  [0603]  (hidden comment: C1608X5R1A474K)
C36  ValueDisplayed: 0.47μF  [0603]  (hidden comment: C1608X5R1A474K)
C37  ValueDisplayed: 0.47μF  [0603]  (hidden comment: C1608X5R1A474K)
D5  SMAJ30CA  value 30V  [SMA]
D7  BZT52C16T-7  [SOD-523]  (value not drawn)
D8  GBLC03-LF-T7  value 3.3V  [sod-323]
D9  D_LED_603  [LED603]
D10  D_LED_603  [LED603]
J8  ED120/3DS  [CONN_ED120_3DS]
J9  ED1817-ND  [CN2P/5.0 -11*12]
J10  JUMPER_2X100MIL  [HDR100_1X2]
L5  XFL4015-471MEC  [XFL4015]  (value not drawn)
L6  XFL4015-471MEC  [XFL4015]  (value not drawn)
L7  XFL4015-471MEC  [XFL4015]  (value not drawn)
Q1  CSD88539ND  [SO-G8/E2.5]  (parts A,B of 2)
Q2  CSD88539ND  [SO-G8/E2.5]  (parts A,B of 2)
Q3  CSD88539ND  [SO-G8/E2.5]  (parts A,B of 2)
Q4  CSD17304Q3  [TRANS_NexFET_Q3]
R8  ValueDisplayed: 0  [0603]  (hidden comment: CRCW06030000Z0EA)
R10  ValueDisplayed: 0  [0603]  (hidden comment: CRCW06030000Z0EA)
R15  ValueDisplayed: 27  [0603]  (hidden comment: CRCW060327R0JNEA)
R16  ValueDisplayed: 10.0k  [0603]  (hidden comment: CRCW060310K0FKEA)
R17  ValueDisplayed: 10.0k  [0603]  (hidden comment: CRCW060310K0FKEA)
R18  ValueDisplayed: 27  [0603]  (hidden comment: CRCW060327R0JNEA)
R19  ValueDisplayed: 1.00  [0603]  (hidden comment: CRCW06031R00FKEA)
R20  ValueDisplayed: 3.9  [0603]  (hidden comment: CRCW06033R90JNEA)
R21  ValueDisplayed: 3.9  [0603]  (hidden comment: CRCW06033R90JNEA)
R22  ValueDisplayed: 3.9  [0603]  (hidden comment: CRCW06033R90JNEA)
R23  ValueDisplayed: 3.9  [0603]  (hidden comment: CRCW06033R90JNEA)
R24  ValueDisplayed: 0.01  [2512]  (hidden comment: CSRN2512FK10L0)
R25  ValueDisplayed: 3.9  [0603]  (hidden comment: CRCW06033R90JNEA)
R26  ValueDisplayed: 3.3  [0603]  (hidden comment: CRCW06033R30JNEA)
R27  ValueDisplayed: 20.0k  [0603]  (hidden comment: CRCW06033K00JNEA)
R28  ValueDisplayed: 3.9  [0603]  (hidden comment: CRCW06033R90JNEA)
R29  ValueDisplayed: 10.0k  [0603]  (hidden comment: CRCW060310K0FKEA)
R30  ValueDisplayed: 10.0k  [0603]  (hidden comment: CRCW060310K0FKEA)
R31  ValueDisplayed: 1.00k  [0603]  (hidden comment: CRCW06031K00FKEA)
R32  ValueDisplayed: 1.00k  [0603]  (hidden comment: CRCW06031K00FKEA)
R33  ValueDisplayed: 40.2k  [0603]  (hidden comment: RC0603FR-0740K2L)
R34  ValueDisplayed: 40.2k  [0603]  (hidden comment: RC0603FR-0740K2L)
R35  ValueDisplayed: 40.2k  [0603]  (hidden comment: RC0603FR-0740K2L)
R36  ValueDisplayed: 40.2k  [0603]  (hidden comment: RC0603FR-0740K2L)
R37  ValueDisplayed: 1.00k  [0603]  (hidden comment: CRCW06031K00FKEA)
R38  ValueDisplayed: 1.00k  [0603]  (hidden comment: CRCW06031K00FKEA)
R39  ValueDisplayed: 1.00k  [0603]  (hidden comment: CRCW06031K00FKEA)
R40  ValueDisplayed: 1.00k  [0603]  (hidden comment: CRCW06031K00FKEA)
R41  ValueDisplayed: 3.60k  [0603]  (hidden comment: RC0603FR-073K6L)
R42  ValueDisplayed: 3.60k  [0603]  (hidden comment: RC0603FR-073K6L)
R43  ValueDisplayed: 3.60k  [0603]  (hidden comment: RC0603FR-073K6L)
R44  ValueDisplayed: 3.60k  [0603]  (hidden comment: RC0603FR-073K6L)
R45  ValueDisplayed: 27  [0603]  (hidden comment: CRCW060327R0JNEA)
TP6  TEMP  [TESTPOINT]  (value not drawn)  (no BOM)
TP7  TESTPOINT  [TESTPOINT]  (value not drawn)  (no BOM)
TP8  TESTPOINT  [TESTPOINT]  (value not drawn)  (no BOM)
TP9  TESTPOINT  [TESTPOINT]  (value not drawn)  (no BOM)
TP10  VA  [TESTPOINT]  (value not drawn)  (no BOM)
TP11  VB  [TESTPOINT]  (value not drawn)  (no BOM)
TP12  VC  [TESTPOINT]  (value not drawn)  (no BOM)
TP13  VM_Monitor  [TESTPOINT]  (value not drawn)  (no BOM)
U5  DRV8303DCA  [DCA0048A_N]
U6  LMT84DCK  [DCK0005A_N]
U7  TPD4S009DBVRG4  [DBV0006A_N]

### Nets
GND: C14.2 C15.2 C20.1 C21.2(-) C24.2 C28.2(-) C29.2 C30.2 C31.2 C32.2 C33.2 C34.2 C35.2 C36.2 C37.2 D5.1 D7.2(A) D9.1(C) D10.1(C) Q4.1(S) Q4.2(S) Q4.3(S) R10.2 R19.1 R24.1 R29.1 R30.1 R41.1 R42.1 R43.1 R44.1 TP7.1 TP8.1 TP9.1 U5.24(AGND) U5.26(SP2) U5.27(SN2) U5.46(GND) U5.47(GND) U5.48(GND) U5.49(PAD) U6.1(GND) U6.2(GND) U6.5(GND) U7.2(GND)
GND_IN: J9.1 Q4.5(D) Q4.6(D) Q4.7(D) Q4.8(D)
GVDD: C20.2 R31.2 U5.9(GVDD)
VM: C14.1 C15.1 C16.2 C17.2 C18.2 C21.1(+) C28.1(+) D5.2 J9.2 Q1.7(D) Q1.8(D) Q2.7(D) Q2.8(D) Q3.7(D) Q3.8(D) R26.1 R27.2 R36.2 U5.25(PVDD)
VREG_3V3: C24.1 C30.1 D8.1(K) R16.2 R17.2 R32.2 U5.20(REF) U5.45(VDD_SPI) U6.4(VDD) U7.5(VCC)
M1_BEMF_VA: C34.1 R37.2 TP10.1 U7.6(D1-) ; off-sheet M1_BEMF_VA
M1_BEMF_VB: C35.1 R38.2 TP11.1 U7.3(D2+) ; off-sheet M1_BEMF_VB
M1_BEMF_VC: C36.1 R39.2 TP12.1 U7.4(D2-) ; off-sheet M1_BEMF_VC
M1_DC_CAL: J10.2 ; off-sheet M1_DC_CAL
M1_EN_GATE: U5.12(EN_GATE) ; off-sheet M1_EN_GATE
M1_FET_TEMP: C31.1 TP6.1 U6.3(OUT) ; off-sheet M1_FET_TEMP
M1_GH_A: Q1.2(G) R20.2
M1_GH_B: Q2.2(G) R22.2
M1_GH_C: Q3.2(G) R25.2
M1_GL_A: Q1.4(G) R21.2
M1_GL_B: Q2.4(G) R23.2
M1_GL_C: Q3.4(G) R28.2
M1_IDC: D8.2(A) U5.21(SO1) ; off-sheet M1_IDC
M1_INH_A: U5.13(INH_A) ; off-sheet M1_INH_A
M1_INH_B: U5.15(INH_B) ; off-sheet M1_INH_B
M1_INH_C: U5.17(INH_C) ; off-sheet M1_INH_C
M1_INL_A: U5.14(INL_A) ; off-sheet M1_INL_A
M1_INL_B: U5.16(INL_B) ; off-sheet M1_INL_B
M1_INL_C: U5.18(INL_C) ; off-sheet M1_INL_C
M1_nFAULT: R17.1 U5.2(~{FAULT}) ; off-sheet M1_nFAULT
M1_nOCTW: R16.1 U5.1(~{OCTW}) ; off-sheet M1_nOCTW
M1_nSCS: U5.4(~{SCS}) ; off-sheet M1_nSCS
M1_OUT_A: C22.1 L5.1 Q1.1(S) Q1.5(D) Q1.6(D) R33.2 U5.42(SH_A)
M1_OUT_B: C25.1 L6.1 Q2.1(S) Q2.5(D) Q2.6(D) R34.2 U5.37(SH_B)
M1_OUT_C: C26.1 L7.1 Q3.1(S) Q3.5(D) Q3.6(D) R35.2 U5.32(SH_C)
M1_SCLK: R15.1 ; off-sheet M1_SCLK
M1_SDI: R18.1 ; off-sheet M1_SDI
M1_SDO: R45.1 ; off-sheet M1_SDO
M1_SL: C16.1 C17.1 C18.1 Q1.3(S) Q2.3(S) Q3.3(S) R8.2 R24.2 U5.30(SL_C) U5.35(SL_B) U5.40(SL_A)
M1_SN1: C27.1 R8.1 U5.29(SN1)
M1_SP1: C27.2 R10.1 U5.28(SP1)
VM_Monitor: C37.1 R40.2 TP13.1 U7.1(D1+) ; off-sheet VM_Monitor
NetC19_1: C19.1 U5.10(CP1)
NetC19_2: C19.2 U5.11(CP2)
NetC22_2: C22.2 U5.44(BST_A)
NetC25_2: C25.2 U5.39(BST_B)
NetC26_2: C26.2 U5.34(BST_C)
NetC29_1: C29.1 R26.2
NetC32_1: C32.1 U5.23(AVDD)
NetC33_1: C33.1 U5.19(DVDD)
NetD7_1: D7.1(K) Q4.4(G) R27.1 R29.2
NetD9_2: D9.2(A) R31.1
NetD10_2: D10.2(A) R32.1
NetJ8_1: J8.1 L5.2
NetJ8_2: J8.2 L6.2
NetJ8_3: J8.3 L7.2
NetJ10_1: J10.1 R30.2 U5.8(DC_CAL)
NetR15_2: R15.2 U5.7(SCLK)
NetR18_2: R18.2 U5.5(SDI)
NetR19_2: R19.2 U5.3(DTC)
NetR20_1: R20.1 U5.43(GH_A)
NetR21_1: R21.1 U5.41(GL_A)
NetR22_1: R22.1 U5.38(GH_B)
NetR23_1: R23.1 U5.36(GL_B)
NetR25_1: R25.1 U5.33(GH_C)
NetR28_1: R28.1 U5.31(GL_C)
NetR33_1: R33.1 R37.1 R41.2
NetR34_1: R34.1 R38.1 R42.2
NetR35_1: R35.1 R39.1 R43.2
NetR36_1: R36.1 R40.1 R44.2
NetR45_2: R45.2 U5.6(SDO)

Not connected (* = marked no-connect by the designer): U5 22(SO2)

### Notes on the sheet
- PWM chopping only on High side.
  Slewrate control only on high side.
  (To keep the shunt current sensing away from switching noise. Recommended by A.G.)
- (near C16) When Slewrate is changed by RC, mind the Deadtime by DTC.
  1ohm -> approx. 50ns
- C16 , C17 and C18 are decoupling capacitors, place close to each bridge of the inverter.
- (near J9) Are Loc necessary for DRV8303?
- nSCS cannot be connected directly to GND.
  SPI logic needs to be reset by high level on nSCS.
- Loc inductors are all place holders.
  Candidate parts are:
  XFL4015-122: 1.2uH
  (Smaller size but lower current.)
  XFL6012-801: 0.8uH
  (Bigger size but higher current.)
- FET temperature sensing circuit.
  Place close to the FET in the middle.
- Bypass capacitor is to be placed within 5cm.
- A place holder for board-to-board connector
- DRV8303 PVDD max at 70V
  DRV10983 VCC max at 30V
- Since trip time of the fuse is rather long (several sec), is the capacitor able to withstand the reversed power supply?
- GND testpoint.
  For easy probing.
- (near TP9) GND testpoint.
  For easy probing.
- Actual resistance to be defined when LED is defined.
- Distribute over the board.
- C34, C35, C36, C37 to be placed as close to the MCU as possible.

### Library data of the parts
C14 C22 C25 C26 = 06035C104KAT2A: CAP, CERM, 0.1 μF, 50 V, +/- 10%, X7R, 0603; Manufacturer: AVX; Polarized: N; CompType: Capacitor; Value: 0.1uF; U/M: EA; Cap_F: 0.0000001; Tolerance_%: 10; Value1: Unknown; VDC_V: 50; Value2: 50V; TaMin_C: -55; TaMax_C: 125
C15 = C2012X5R1H475K125AB: CAP, CERM, 4.7 μF, 50 V, +/- 10%, X5R, 0805; Manufacturer: TDK; Polarized: N; CompType: Capacitor; Value: 4.7uF; U/M: EA; Cap_F: 0.0000047; Tolerance_%: 10; Value1: Unknown; VDC_V: 50; Value2: 50V; TaMin_C: -55; TaMax_C: 85; Cap_Case: 0805
C16-C18 = C2012X7R1H105K125AB: CAP, CERM, 1 μF, 50 V, +/- 10%, X7R, 0805; Manufacturer: TDK; Polarized: N; CompType: Capacitor; Value: 1uF; U/M: EA; Cap_F: 0.000001; Tolerance_%: 10; Value1: Unknown; VDC_V: 50; Value2: 50V; TaMin_C: -55; TaMax_C: 125; Cap_Case: 0805
C19 = C1608X8R1H223K: CAP, CERM, 0.022 μF, 50 V, +/- 10%, X8R, 0603; Manufacturer: TDK; Polarized: N; CompType: Capacitor; Value: 0.022uF; U/M: EA; Cap_F: 0.000000022; Tolerance_%: 10; ESR_ohm: 0.0409; Value1: 0.0409 ohm; VDC_V: 50; Value2: 50V; TaMin_C: -55; TaMax_C: 150
C20 = C2012X7R1V225K085AC: CAP, CERM, 2.2 μF, 35 V, +/- 10%, X7R, 0805; Manufacturer: TDK; Polarized: N; CompType: Capacitor; Value: 2.2uF; U/M: EA; Cap_F: 0.0000022; Tolerance_%: 10; Value1: Unknown; VDC_V: 35; Value2: 35V; TaMin_C: -55; TaMax_C: 125; Cap_Case: 0805
C21 C28 = EEHZA1V271P: CAP, AL, 270 μF, 35 V, +/- 20%, 20 ohm, SMD; Manufacturer: Panasonic; Polarized: Y; CompType: Capacitor; Value: 270uF; U/M: EA; Cap_F: 0.00027; Tolerance_%: 20; Value1: 20 ohm; VDC_V: 35; Value2: 35V; IRMS_A: 2.5; TaMin_C: -55; TaMax_C: 105
C24 = C0603X104K8RACTU: CAP, CERM, 0.1 μF, 10 V, +/- 10%, X7R, 0603; Manufacturer: Kemet; Polarized: N; CompType: Capacitor; Value: 0.1uF; U/M: EA; Cap_F: 0.0000001; Tolerance_%: 10; Value1: Unknown; Value2: 10V; TaMin_C: -55; TaMax_C: 125
C27 = C1608C0G1H102J: CAP, CERM, 1000 pF, 50 V, +/- 5%, C0G/NP0, 0603; Manufacturer: TDK; Polarized: N; CompType: Capacitor; Value: 1000pF; U/M: EA; Cap_F: 0.000000001; Tolerance_%: 5; ESR_ohm: 0.0563; Value1: 0.0563 ohm; VDC_V: 50; Value2: 50V; TaMin_C: -55; TaMax_C: 125
C29 = 08055C103JAT2A: CAP, CERM, 0.01 μF, 50 V, +/- 5%, X7R, 0805; Manufacturer: AVX; Polarized: N; CompType: Capacitor; Value: 0.01uF; U/M: EA; Cap_F: 0.00000001; Tolerance_%: 5; ESR_ohm: 0.078; Value1: 0.078 ohm; VDC_V: 50; Value2: 50V; TaMin_C: -55; TaMax_C: 125; Cap_Case: 0805
C30 C31 = C1608C0G1E103J: CAP, CERM, 0.01 μF, 25 V, +/- 5%, C0G/NP0, 0603; Manufacturer: TDK; Polarized: N; CompType: Capacitor; Value: 0.01uF; U/M: EA; Cap_F: 0.00000001; Tolerance_%: 5; Value1: Unknown; VDC_V: 25; Value2: 25V; TaMin_C: -55; TaMax_C: 125
C32 C33 = C1608X5R1E105K080AC: CAP, CERM, 1 μF, 25 V, +/- 10%, X5R, 0603; Manufacturer: TDK; Polarized: N; CompType: Capacitor; Value: 1uF; U/M: EA; Cap_F: 0.000001; Tolerance_%: 10; Value1: Unknown; VDC_V: 25; Value2: 25V; TaMin_C: -55; TaMax_C: 85
C34-C37 = C1608X5R1A474K: CAP, CERM, 0.47 μF, 10 V, +/- 10%, X5R, 0603; Manufacturer: TDK; Polarized: N; CompType: Capacitor; Value: 0.47uF; U/M: EA; Cap_F: 0.00000047; Tolerance_%: 10; ESR_ohm: 0.0101; Value1: 0.0101 ohm; Value2: 10V; TaMin_C: -55; TaMax_C: 85
D5 = SMAJ30CA: Diode, TVS, Bi, 30 V, 400 W, SMA; Manufacturer: Littelfuse; U/M: EA; Power_W: 400; Vr_V: 30; Value1: 400W; RJA_CperW: 120
D7 = BZT52C16T-7: Diode, Zener, 16 V, 300 mW, SOD-523; Manufacturer: Diodes Inc.; SymbolCreator: a0412235; Value: 16V; U/M: EA; Power_W: 0.3; Vz_V: 16; Value1: 0.3W; RJA_CperW: 417
D8 = GBLC03-LF-T7: Diode, TVS, Uni, 3.3 V, 350 W, SOD-323; Manufacturer: Protek Devices; U/M: EA; Power_W: 350; Vr_V: 3.3; Value1: 350W
D9 D10 = D_LED_603: as D1 on sheet TIDA00447_MCU+DRV10983
J8 = ED120/3DS: as J2 on sheet TIDA00447_MCU+DRV10983
J9 = ED120/2DS: TERMINAL BLOCK 5.08MM VERT 2POS, TH; Manufacturer: Molex; SymbolCreator: a0412235; CompType: 2 position header; U/M: EA
J10 = JUMPER_2X100MIL: Header, Male 2-pin, 100mil spacing,; Manufacturer: Sullins; PartNumber: PEC02SAAN; area: 20000; Value: PEC02SAAN
L5-L7 = XFL4015-471MEC: Inductor, Shielded, Composite, 470 nH, 3.5 A, 0.0076 ohm, SMD; Manufacturer: Coilcraft; Value: 470nH; Ind_H: 470.0E-9; Imax_A: 3.5; Irms: 9.1A @ 20C rise; Isat: 3.5A @ 10% inductance drop; DCR_ohm: 0.0076; Value2: 3.5A
Q1-Q3 = CSD88539ND: MOSFET, N-CH, 60 V, 6.3 A, SO-8; Manufacturer: Texas Instruments; Alternate Manufacturer: None; U/M: EA; ChType: N; Value: 60V; VdsMax_V: 60; Value1: ? ohm; Value2: 7.2 nC; QgTyp_nC: 7.2; Vgs_V: 20; IdsMax_A: 6.3
Q4 = CSD17304Q3: MOSFET, N-CH, 30 V, 56 A, SON 3.3x3.3mm; Manufacturer: Texas Instruments; Alternate Manufacturer: None; U/M: EA; ChType: N; Value: 30V; VdsMax_V: 30; Value1: 0.0069 ohm; Rdson45_ohm: 0.0069; Value2: 5.1 nC; QgTyp_nC: 5.1; Vgs_V: 10; IdsMax_A: 56
R8 R10 = CRCW06030000Z0EA: RES, 0, 5%, 0.1 W, 0603; Manufacturer: Vishay-Dale; CompType: Resistor; Value: 0; Value_Code: 0000; Tolerance_%: 5; Power_W: 0.1; Value2: 0.1W; VDC_V: 75; TempCo: 200 ppm/C; EIA_Code: E24; U/M: EA
R15 R18 R45 = CRCW060327R0JNEA: RES, 27, 5%, 0.1 W, 0603; Manufacturer: Vishay-Dale; CompType: Resistor; Value: 27; Value_Code: 27R0; Tolerance_%: 5; Power_W: 0.1; Value2: 0.1W; VDC_V: 75; TempCo: 200 ppm/C; EIA_Code: E24; U/M: EA
R16 R17 R29 R30 = CRCW060310K0FKEA: RES, 10.0 k, 1%, 0.1 W, 0603; Manufacturer: Vishay-Dale; CompType: Resistor; Value: 10.0k; Res_ohm: 10000; Value_Code: 10k0; Tolerance_%: 1; Power_W: 0.1; Value2: 0.1W; VDC_V: 75; TempCo: 100 ppm/C; EIA_Code: E96; U/M: EA
R19 = CRCW06031R00FKEA: RES, 1.00, 1%, 0.1 W, 0603; Manufacturer: Vishay-Dale; CompType: Resistor; Value: 1.00; Res_ohm: 1; Value_Code: 1R00; Power_W: 0.1; Value2: 0.1W; VDC_V: 75; TempCo: 100 ppm/C; EIA_Code: E96; U/M: EA
R20-R23 R25 R28 = CRCW06033R90JNEA: RES, 3.9, 5%, 0.1 W, 0603; Manufacturer: Vishay-Dale; CompType: Resistor; Value: 3.9; Value_Code: 3R90; Tolerance_%: 5; Power_W: 0.1; Value2: 0.1W; VDC_V: 75; TempCo: 200 ppm/C; EIA_Code: E24; U/M: EA
R24 = CSRN2512FK10L0: RES, 0.01, 1%, 2 W, 2512; Manufacturer: Stackpole Electronics Inc; CompType: Resistor; Value: 0.01; Value_Code: R010; Tolerance_%: 1; Power_W: 2; Value2: 2W; TempCo: 200 ppm/C; EIA_Code: E96; U/M: EA
R26 = CRCW06033R30JNEA: RES, 3.3, 5%, 0.1 W, 0603; Manufacturer: Vishay-Dale; CompType: Resistor; Value: 3.3; Value_Code: 3R30; Tolerance_%: 5; Power_W: 0.1; Value2: 0.1W; VDC_V: 75; TempCo: 200 ppm/C; EIA_Code: E24; U/M: EA
R27 = CRCW06033K00JNEA: RES, 3.0 k, 5%, 0.1 W, 0603; Manufacturer: Vishay-Dale; CompType: Resistor; Value: 3.0k; Res_ohm: 3000; Value_Code: 3k00; Tolerance_%: 5; Power_W: 0.1; Value2: 0.1W; VDC_V: 75; TempCo: 200 ppm/C; EIA_Code: E24; U/M: EA
R31 R32 R37-R40 = CRCW06031K00FKEA: RES, 1.00 k, 1%, 0.1 W, 0603; Manufacturer: Vishay-Dale; CompType: Resistor; Value: 1.00k; Res_ohm: 1000; Value_Code: 1k00; Tolerance_%: 1; Power_W: 0.1; Value2: 0.1W; VDC_V: 75; TempCo: 100 ppm/C; EIA_Code: E96; U/M: EA
R33-R36 = RC0603FR-0740K2L: RES, 40.2 k, 1%, 0.1 W, 0603; Manufacturer: Yageo America; CompType: Resistor; Value: 40.2k; Res_ohm: 40200; Value_Code: 40k2; Tolerance_%: 1; Power_W: 0.1; Value2: 0.1W; VDC_V: 150; TempCo: 200 ppm/C; EIA_Code: E96; U/M: EA
R41-R44 = RC0603FR-073K6L: RES, 3.60 k, 1%, 0.1 W, 0603; Manufacturer: Yageo America; CompType: Resistor; Value: 3.60k; Res_ohm: 3600; Value_Code: 3k60; Tolerance_%: 1; Power_W: 0.1; Value2: 0.1W; VDC_V: 150; TempCo: 200 ppm/C; U/M: EA
TP6-TP13 = TESTPOINT: TEST POINT.  No entry in BOM.
U5 = DRV8303DCA: THREE PHASE PRE-DRIVER WITH DUAL CURRENT SHUNT AMPLIFIERS, DCA0048A; Manufacturer: Texas Instruments; SymbolCreator: x0208325; CompType: IC; U/M: EA
U6 = LMT84DCK: Analog Temperature Sensors with Class-AB Output, DCK0005A; Manufacturer: Texas Instruments; SymbolCreator: a0799628; CompType: IC; U/M: EA
U7 = TPD4S009DBVRG4: ESD Solution for High-Speed Differential Interface, 4 Channels, -40 to +85 degC, 6-pin SOT-23 (DBV), Green (RoHS & no Sb/Br); Manufacturer: Texas Instruments; Alternate Manufacturer: None; Alternate PartNumber: Equivalent; Breakdown Voltage(Min)(V): 9; Differential Capacitance(pF): 0.05; IEC 61000-4-2 Contact(+/- kV): 8; IO Capacitance(Typ)(pF): 0.8; IO Leakage Current(nA): 10

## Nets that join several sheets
GND: TIDA00447_MCU+DRV10983 (22 pins), TIDA00447_DRV8303 (45 pins)
VM: TIDA00447_MCU+DRV10983 (5 pins), TIDA00447_DRV8303 (19 pins)
VREG_3V3: TIDA00447_MCU+DRV10983 (11 pins), TIDA00447_DRV8303 (10 pins)
M1_BEMF_VA: TIDA00447_MCU+DRV10983 (U1.28), TIDA00447_DRV8303 (C34.1 R37.2 TP10.1 U7.6)
M1_BEMF_VB: TIDA00447_MCU+DRV10983 (U1.8), TIDA00447_DRV8303 (C35.1 R38.2 TP11.1 U7.3)
M1_BEMF_VC: TIDA00447_MCU+DRV10983 (U1.30), TIDA00447_DRV8303 (C36.1 R39.2 TP12.1 U7.4)
M1_DC_CAL: TIDA00447_MCU+DRV10983 (TP1.1 U1.34), TIDA00447_DRV8303 (J10.2)
M1_EN_GATE: TIDA00447_MCU+DRV10983 (U1.3), TIDA00447_DRV8303 (U5.12)
M1_FET_TEMP: TIDA00447_MCU+DRV10983 (U1.11), TIDA00447_DRV8303 (C31.1 TP6.1 U6.3)
M1_IDC: TIDA00447_MCU+DRV10983 (U1.23), TIDA00447_DRV8303 (D8.2 U5.21)
M1_INH_A: TIDA00447_MCU+DRV10983 (U1.37), TIDA00447_DRV8303 (U5.13)
M1_INH_B: TIDA00447_MCU+DRV10983 (U1.33), TIDA00447_DRV8303 (U5.15)
M1_INH_C: TIDA00447_MCU+DRV10983 (U1.29), TIDA00447_DRV8303 (U5.17)
M1_INL_A: TIDA00447_MCU+DRV10983 (U1.20), TIDA00447_DRV8303 (U5.14)
M1_INL_B: TIDA00447_MCU+DRV10983 (U1.21), TIDA00447_DRV8303 (U5.16)
M1_INL_C: TIDA00447_MCU+DRV10983 (U1.22), TIDA00447_DRV8303 (U5.18)
M1_nFAULT: TIDA00447_MCU+DRV10983 (U1.36), TIDA00447_DRV8303 (R17.1 U5.2)
M1_nOCTW: TIDA00447_MCU+DRV10983 (U1.35), TIDA00447_DRV8303 (R16.1 U5.1)
M1_nSCS: TIDA00447_MCU+DRV10983 (U1.10), TIDA00447_DRV8303 (U5.4)
M1_SCLK: TIDA00447_MCU+DRV10983 (U1.9), TIDA00447_DRV8303 (R15.1)
M1_SDI: TIDA00447_MCU+DRV10983 (U1.5), TIDA00447_DRV8303 (R18.1)
M1_SDO: TIDA00447_MCU+DRV10983 (U1.6), TIDA00447_DRV8303 (R45.1)
VM_Monitor: TIDA00447_MCU+DRV10983 (U1.27), TIDA00447_DRV8303 (C37.1 R40.2 TP13.1 U7.1)

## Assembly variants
Only Populated Components: not fitted C34 C35 C36 FID1 FID2 FID3 R1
